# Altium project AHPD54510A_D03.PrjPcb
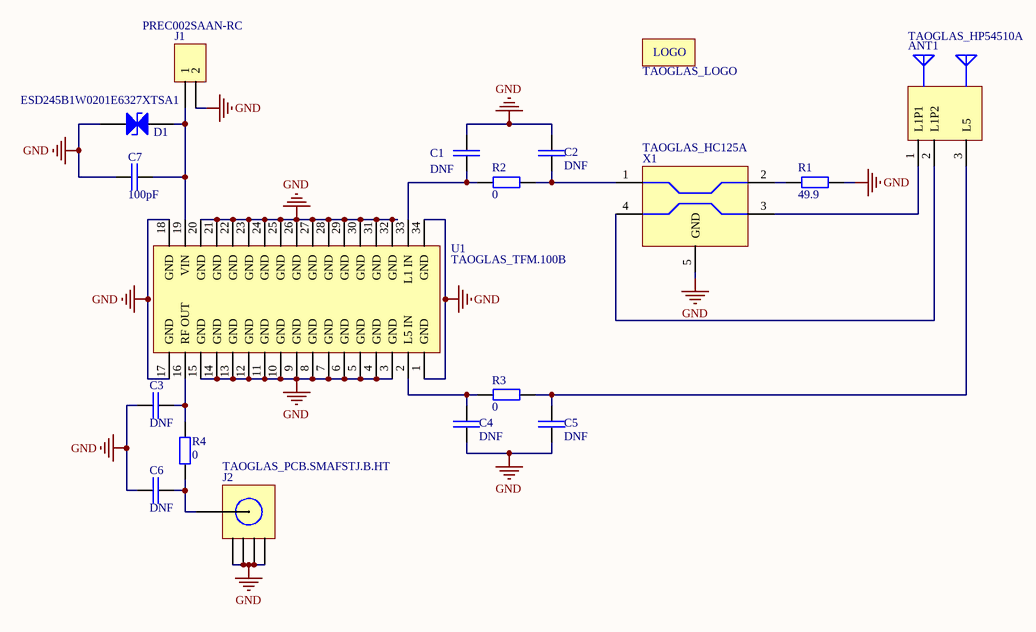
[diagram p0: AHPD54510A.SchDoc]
1 sheet, 18 parts. Net scope: global (net labels, ports and power ports of the same name join across sheets).
Board file: AHPD54510A_D03.PcbDoc

## Sheet AHPD54510A.SchDoc
size Tabloid; SheetNumber: 1; SheetTotal: 1

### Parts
ANT1  TAOGLAS_HP54510A  [TAOGLAS_HP54510A]
C1  DNF  [0402 - DNF]
C2  DNF  [0402 - DNF]
C3  DNF  [0402 - DNF]
C4  DNF  [0402 - DNF]
C5  DNF  [0402 - DNF]
C6  DNF  [0402 - DNF]
C7  value 100pF  [Capacitor - 0402 - GRM]  (hidden comment: Capacitor_Ceramic_1005(0402)_L1_W0.5_H0.5mm_100pF+-5%_50V_-55 to 125C_Murata_GRM1555C1H101JA01)
D1  ESD245B1W0201E6327XTSA1  [Diode - 0201 (0603 Metric) - DSN0603-2]
J1  PREC002SAAN-RC  [SULLINS_PREC002SAAN-RC]
J2  TAOGLAS_PCB.SMAFSTJ.B.HT  [TAOGLAS_PCB.SMAFSTJ.B.HT]
LOGO  TAOGLAS_LOGO  [TAOGLAS_LOGO - No R - 10.3mm]  (no BOM)
R1  value 49.9  [Resistor - 0402 - ERJ-2RK]  (hidden comment: Resistor_Thick Film_1005(0402)_49.9Ohms+-1%_0.1W)
R2  value 0  [Resistor - 0402 - RC_L]  (hidden comment: Resistor_Thick Film_1005(0402)_0Ohm)
R3  value 0  [Resistor - 0402 - RC_L]  (hidden comment: Resistor_Thick Film_1005(0402)_0Ohm)
R4  value 0  [Resistor - 0402 - RC_L]  (hidden comment: Resistor_Thick Film_1005(0402)_0Ohm)
U1  TAOGLAS_TFM.100B  [TAOGLAS_TFM.100B]
X1  TAOGLAS_HC125A  [TAOGLAS_HC125A]

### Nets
GND: C1.2 C2.1 C3.1 C4.1 C5.2 C6.2 C7.1 D1.2(ANODE) J1.2 J2.2(GND) J2.3(GND) J2.4(GND) J2.5(GND) R1.2 U1.1(GND) U1.3(GND) U1.4(GND) U1.5(GND) U1.6(GND) U1.7(GND) U1.8(GND) U1.9(GND) U1.10(GND) U1.11(GND) U1.12(GND) U1.13(GND) U1.14(GND) U1.15(GND) U1.17(GND) U1.18(GND) U1.20(GND) U1.21(GND) U1.22(GND) U1.23(GND) U1.24(GND) U1.25(GND) U1.26(GND) U1.27(GND) U1.28(GND) U1.29(GND) U1.30(GND) U1.31(GND) U1.32(GND) U1.34(GND) X1.5(GND)
NetANT1_1: ANT1.1(L1P1) X1.3
NetANT1_2: ANT1.2(L1P2) X1.4
NetANT1_3: ANT1.3(L5) C5.1 R3.2
NetC1_1: C1.1 R2.1 U1.33(L1_IN)
NetC2_2: C2.2 R2.2 X1.1
NetC3_2: C3.2 R4.2 U1.16(RF_OUT)
NetC4_2: C4.2 R3.1 U1.2(L5_IN)
NetC6_1: C6.1 J2.1 R4.1
NetC7_2: C7.2 D1.1(CATHODE) J1.1 U1.19(VIN)
NetR1_1: R1.1 X1.2

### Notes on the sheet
- Labels drawn without touching a wire or pin: GND

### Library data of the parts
ANT1 = CMP-270-000002-3: Passive Multiband High Precision GNSS L1/L5 Stacked Patch Antenna; Temp_Low: -40C; Temp_High: +85C; ComponentLibStatus: Created
C1-C6 = CMP-00006-25: Do Not Fit
C7 = CMP-001-00343-45: 100 pF ±5% 50V Ceramic Capacitor C0G, NP0 0402 (1005 Metric); MFG: Murata Electronics; Product Status: Not For New Designs; MFGPN: GRM1555C1H101JA01D
D1 = CMP-004-00167-10: 7.5V Clamp 5.5A (8/20µs) Ipp Tvs Diode Surface Mount WLL-2-3; MFG: Infineon Technologies; Type: Zener; Voltage - Reverse Standoff (Typ): 5.5V; Capacitance @ Frequency: 5.8pF @ 1GHz; Power Line Protection: No; Base Product Number: ESD245; Bidirectional Channels: 1; Power - Peak Pulse: 44W
J1 = CMP-002-00180-7: Connector Header Through Hole 2 position 0.100" (2.54mm); MFG: Sullins Connector Solutions; Product Status: Active; Connector Type: BOARD CONNECTOR; Number of Positions: 2; Temp_High: 105°C; Temp_Low: -40°C; Angle: 180°
J2 = CMP-028-000009-10: SMA (F) Surface Mount PCB Jack; ComponentLibStatus: Created; Temp_Low: -40C; Temp_High: +85C
LOGO = CMP-048-000000-3: Silkscreen Logo - Standard
R1 = CMP-009-00256-10: 49.9 Ohms ±1% 0.1W, 1/10W Chip Resistor 0402 (1005 Metric) Automotive AEC-Q200 Thick Film; MFG: Panasonic Electronic Components; Product Status: Active; MFGPN: ERJ-2RKF49R9X; Temperature Coefficient: ±100ppm/°C; Power (Watts): 100mW
R2-R4 = CMP-009-00375-4: 0 Ohms Jumper Chip Resistor 0402 (1005 Metric) Moisture Resistant Thick Film; Product Status: Active; MFGPN: RC0402JR-070RL; MFG: YAGEO
U1 = CMP-266-000001-10: Surface mount GNSS front-end module covering L1/L5; Temp_High: +85C; ComponentLibStatus: Created; Temp_Low: -40C
X1 = CMP-002-000151-19: Low Profile, High Performance Multiband GNSS Hybrid Coupler; Product Status: Active; Center Frequency: 1.39GHz; MFGPN: HC125A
